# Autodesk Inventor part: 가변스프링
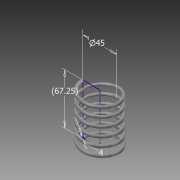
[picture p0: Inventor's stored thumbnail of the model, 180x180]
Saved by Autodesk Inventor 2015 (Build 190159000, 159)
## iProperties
Created: 2016-02
Part Number: 가변스프링
Material: 스테인레스 스틸
Document SubType Name: Modeling
Designer: Administrator
Mass: 84.3791 g
Surface Area: 106.606 cm^2
Volume: 10.5474 cm^3
Density: 8 g/cm^3
Appearance: 반연마
Author: Administrator
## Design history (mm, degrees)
sketch "스케치1"
  geometry: L1 (0, 0)-(22.5, 0); L2 (22.5, 0)-(22.5, 67.25); L3 (22.5, 67.25)-(0, 67.25); L4 (0, 67.25)-(0, 0); C1 r 2 at (22.5, 0)
  constraints: 8 end point, 2 parallel, 1 centre point, 1 coincident, 1 horizontal, 1 perpendicular
  dimensions: "d0" = 45 diameter of L2 L4; "d1" = 67.25 distance between parallel lines of L1 L3 (derived); "d2" = 4 diameter of C1
feature "코일1" sketch "스케치1" pitch "d3" = 10; turns "d5" = 6; dims "d4" = 67.25 (= d1), "d6" = 0, angle "d7" = 90 deg, angle "d8" = 90 deg, "d9" = 0, "d10" = 0
sketch "스케치2"
  geometry: L1 (-20.5, 0)-(-24.5, 0) reference; 1 further point
  constraints: 1 horizontal alignment
extrude "돌출1" cut sketch "스케치2" stored distance "d11" = 10; taper "d12" = 0 deg
node "작업 평면1"
sketch "스케치3"
  geometry: L1 (20.5, 0)-(24.5, 0) reference; 1 further point
  constraints: 1 horizontal alignment
extrude "돌출2" cut sketch "스케치3" stored distance "d13" = 10; taper "d14" = 0 deg
node "솔리드1"
node "절단 모서리 투영1"
node "절단 모서리 투영2"
